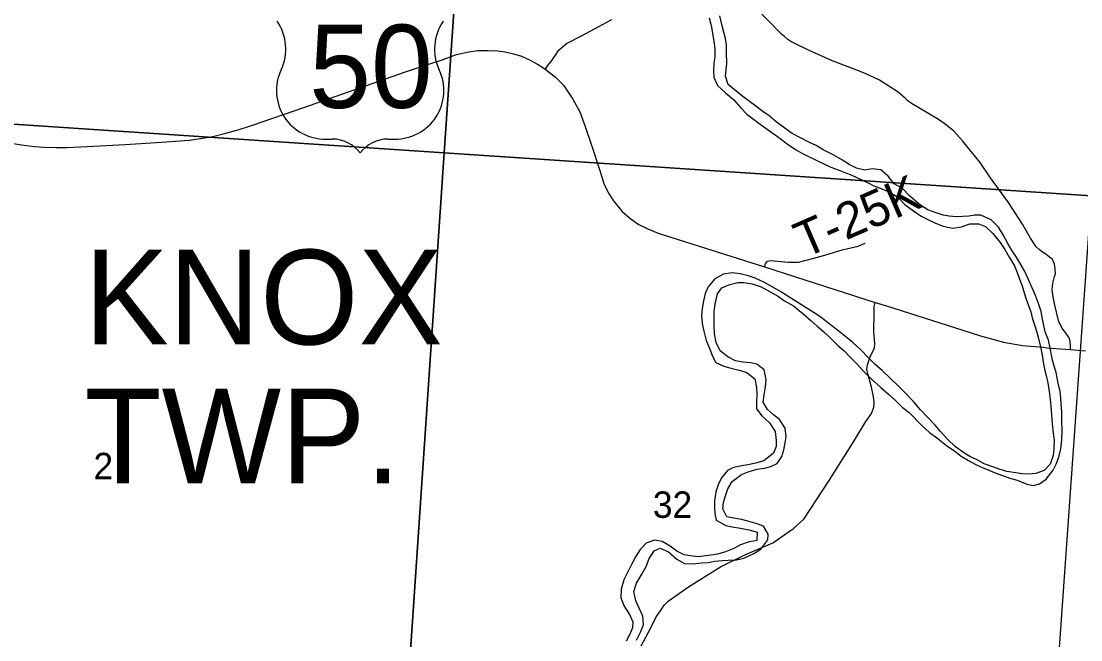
# Model space of a CAD drawing. Extents: x 0 to 34, y 0 to 22.
# Drawn here: x 3.724 to 5.404, y 16.952 to 17.932 of the extents above; entities that cross this region are included whole.
import ezdxf

# ---------------------------------------------------------------- set-up
doc = ezdxf.new("R2010")
doc.units = 0
for name, color, linetype in [('GM_X_Corporation', 7, 'Continuous'), ('GM_X_County_Road', 7, 'Continuous'), ('GM_X_Major_River', 7, 'Continuous'), ('GM_X_Section_Text', 7, 'Continuous'), ('GM_X_State_Route', 7, 'Continuous'), ('GM_X_Township_Road', 7, 'Continuous'), ('GM_X_Township_Road_Text', 7, 'Continuous'), ('GM_X_Township_Text', 7, 'Continuous'), ('GM_X_US_Location', 7, 'Continuous'), ('GM_X_US_Route', 7, 'Continuous'), ('GM_X_US_Shield', 7, 'Continuous')]:
    doc.layers.add(name, color=color, linetype=linetype)

msp = doc.modelspace()

# ---------------------------------------------------------------- linework, layer by layer
at = {"layer": 'GM_X_Corporation'}
for points in [[(4.465, 18.749), (4.3947, 17.724), (3.3856, 17.7912), (3.4438, 18.6342), (3.459, 18.812)], [(5.4857, 18.6848), (5.4744, 18.5035), (5.4208, 17.6557), (4.3947, 17.724), (4.465, 18.749)], [(3.3856, 17.7912), (4.3947, 17.724), (4.3249, 16.693), (3.312, 16.7534)], [(5.4208, 17.6557), (5.3461, 16.6042), (4.3249, 16.693), (4.3947, 17.724)]]:
    msp.add_lwpolyline(points, close=True, dxfattribs=at)
at = {"layer": 'GM_X_County_Road'}
msp.add_lwpolyline([(4.6598, 17.9349), (4.6119, 17.9087), (4.5894, 17.8969), (4.5814, 17.8905), (4.5749, 17.885), (4.5638, 17.8684), (4.5582, 17.8618), (4.5548, 17.8564)], dxfattribs=at)
at = {"layer": 'GM_X_Major_River'}
for points in [[(4.8149, 17.9379), (4.8179, 17.9258), (4.8209, 17.9102), (4.8224, 17.9004), (4.8239, 17.8886), (4.8239, 17.8753), (4.8224, 17.8658), (4.8216, 17.8533)], [(4.8418, 17.8548), (4.8429, 17.8662), (4.8425, 17.8825), (4.8422, 17.8947), (4.841, 17.9053), (4.8358, 17.925), (4.8316, 17.941)], [(4.8216, 17.8533), (4.8224, 17.8438), (4.8284, 17.8305), (4.8406, 17.8191), (4.8539, 17.8081), (4.8649, 17.7952), (4.8747, 17.7853), (4.885, 17.7774), (4.896, 17.7694), (4.9108, 17.7587), (4.9233, 17.7496), (4.9388, 17.7382), (4.9521, 17.7291), (4.9631, 17.723), (4.9867, 17.7112), (4.9977, 17.7059), (5.0079, 17.7014), (5.0197, 17.6968), (5.0299, 17.6926), (5.0413, 17.6884), (5.066, 17.677), (5.0762, 17.6717), (5.0888, 17.6668), (5.1028, 17.6603), (5.1142, 17.6535), (5.1252, 17.6421), (5.1389, 17.6322), (5.151, 17.6235), (5.1616, 17.6181), (5.1738, 17.6124), (5.1859, 17.6079), (5.2007, 17.6044), (5.2152, 17.6067), (5.2281, 17.6113), (5.2425, 17.6112), (5.2531, 17.6071), (5.2649, 17.5961), (5.2763, 17.5816), (5.2838, 17.5706), (5.2907, 17.5588), (5.299, 17.5448), (5.3036, 17.5345), (5.307, 17.5235), (5.3111, 17.5133), (5.3145, 17.5023), (5.3179, 17.492), (5.3213, 17.4822), (5.3248, 17.4719), (5.3274, 17.4624), (5.3308, 17.4514), (5.3346, 17.44), (5.3372, 17.4298), (5.3406, 17.4165), (5.3429, 17.4032), (5.3444, 17.3922), (5.3467, 17.3812), (5.3493, 17.3709), (5.352, 17.3595), (5.3542, 17.3459), (5.3558, 17.3334), (5.3565, 17.322), (5.358, 17.3087), (5.3587, 17.2943), (5.3606, 17.2798), (5.3618, 17.2688), (5.3617, 17.2548), (5.3606, 17.2442), (5.3556, 17.2305), (5.3461, 17.2206), (5.3332, 17.2157), (5.3215, 17.215), (5.3108, 17.2154), (5.3013, 17.2169), (5.2869, 17.2192), (5.2748, 17.2226), (5.2649, 17.2264), (5.2508, 17.2313), (5.2391, 17.2378), (5.2281, 17.2427), (5.2186, 17.2484), (5.2057, 17.2579), (5.1928, 17.2705), (5.1818, 17.2826), (5.1731, 17.2925), (5.1503, 17.3168), (5.1389, 17.3301), (5.1245, 17.3445), (5.115, 17.3544), (5.1025, 17.3662), (5.0896, 17.3783), (5.0775, 17.389), (5.0684, 17.3988), (5.0547, 17.4121), (5.0426, 17.4232), (5.0289, 17.4345), (5.0164, 17.4448), (5.0027, 17.4551), (4.9921, 17.4634), (4.9815, 17.4706), (4.969, 17.4782), (4.9553, 17.487)], [(4.986, 17.4494), (4.9966, 17.4403), (5.0065, 17.4315), (5.0186, 17.4194), (5.0289, 17.4103), (5.0384, 17.4004), (5.049, 17.3897), (5.0589, 17.3784), (5.0718, 17.3658), (5.0873, 17.3521), (5.0994, 17.3415), (5.1104, 17.3313), (5.1211, 17.321), (5.1321, 17.3123), (5.1522, 17.2921), (5.1643, 17.2807), (5.1776, 17.2712), (5.1916, 17.2599), (5.2038, 17.2519), (5.2144, 17.2435), (5.2262, 17.2363), (5.2368, 17.2306), (5.2467, 17.2257), (5.2584, 17.2211), (5.2713, 17.2158), (5.2816, 17.212), (5.2918, 17.2085), (5.3032, 17.2051), (5.3188, 17.1987), (5.3294, 17.1971), (5.3389, 17.1994), (5.3495, 17.207), (5.3602, 17.2214), (5.3651, 17.2309), (5.3693, 17.2415), (5.3728, 17.2552), (5.3743, 17.2692), (5.3747, 17.2844), (5.3743, 17.2988), (5.3743, 17.3136), (5.3732, 17.3258), (5.3725, 17.3356), (5.3713, 17.3459), (5.3683, 17.3592), (5.3653, 17.3759), (5.3623, 17.3857), (5.3596, 17.3956), (5.3555, 17.4146), (5.3528, 17.4271), (5.3479, 17.4404), (5.3456, 17.4506), (5.3437, 17.4605), (5.3415, 17.4723), (5.3373, 17.4852), (5.3324, 17.4977), (5.321, 17.5243), (5.3149, 17.5372), (5.3077, 17.5497), (5.3013, 17.56), (5.2945, 17.5702), (5.2888, 17.5801), (5.2812, 17.5941), (5.2736, 17.6063), (5.2619, 17.6177), (5.2455, 17.6253), (5.2361, 17.6249), (5.2266, 17.6238), (5.2171, 17.623), (5.2072, 17.6223), (5.1954, 17.6234), (5.1859, 17.625), (5.1734, 17.6295), (5.1616, 17.6337), (5.1499, 17.6409), (5.1339, 17.6546), (5.121, 17.6679), (5.1081, 17.6747), (5.099, 17.6869), (5.0873, 17.6971), (5.0736, 17.6987), (5.0618, 17.6964), (5.0485, 17.6994), (5.0368, 17.7055), (5.0262, 17.7124), (5.0129, 17.72), (4.9958, 17.7287), (4.9848, 17.7355), (4.9738, 17.7405), (4.9609, 17.7473), (4.9468, 17.7545), (4.9351, 17.7629), (4.9214, 17.7732), (4.91, 17.7823), (4.8998, 17.7895), (4.8892, 17.7978), (4.8766, 17.807), (4.866, 17.8149), (4.8546, 17.8241), (4.8452, 17.832), (4.841, 17.8453), (4.8418, 17.8548)], [(4.9553, 17.487), (4.9443, 17.4934), (4.9295, 17.5033), (4.9158, 17.5109), (4.9018, 17.5189), (4.8878, 17.5254), (4.8775, 17.5292), (4.8642, 17.5322), (4.8513, 17.5337), (4.8373, 17.5318), (4.8236, 17.5239), (4.8133, 17.5117), (4.8087, 17.5011), (4.8053, 17.4867), (4.8038, 17.4765), (4.803, 17.4666), (4.8041, 17.4537), (4.8064, 17.4412), (4.8102, 17.4264), (4.8159, 17.4127), (4.82, 17.4017), (4.8257, 17.3918), (4.8382, 17.3857), (4.8515, 17.3823), (4.8652, 17.3789), (4.8754, 17.3755), (4.8872, 17.3656), (4.8902, 17.3519), (4.8906, 17.3424), (4.8898, 17.3276), (4.8898, 17.3181), (4.8985, 17.3071), (4.9107, 17.2961), (4.9194, 17.2824), (4.9213, 17.268), (4.9213, 17.2585), (4.9171, 17.2479), (4.9015, 17.2361), (4.889, 17.2324), (4.8764, 17.2297), (4.8666, 17.2282), (4.8537, 17.2252), (4.8438, 17.2206), (4.8343, 17.2089), (4.8293, 17.1979), (4.8255, 17.1869), (4.8236, 17.1728), (4.8236, 17.1626), (4.824, 17.152), (4.8262, 17.1421), (4.8414, 17.1333), (4.8513, 17.1314), (4.8646, 17.1292), (4.8786, 17.1265), (4.8908, 17.1227), (4.8907, 17.1098), (4.8767, 17.1071), (4.8645, 17.103), (4.8539, 17.0969), (4.841, 17.0916), (4.8281, 17.0882), (4.8178, 17.0867), (4.7981, 17.0837), (4.7886, 17.0848), (4.7753, 17.0871), (4.7635, 17.0928), (4.7533, 17.1008), (4.7404, 17.108), (4.7282, 17.1103), (4.7149, 17.1053), (4.7054, 17.0955), (4.6982, 17.0837), (4.6917, 17.0716), (4.6796, 17.0473), (4.6754, 17.0325), (4.675, 17.0188), (4.6799, 17.0056), (4.6886, 16.9926), (4.6939, 16.9809), (4.6935, 16.9714), (4.6886, 16.96), (4.6833, 16.9501)], [(4.6996, 16.952), (4.7064, 16.9653), (4.711, 16.9763), (4.7099, 16.9896), (4.7038, 17.0025), (4.6989, 17.0143), (4.6955, 17.0287), (4.6997, 17.042), (4.708, 17.0564), (4.7153, 17.0697), (4.7195, 17.0803), (4.7275, 17.0932), (4.7373, 17.0977), (4.7502, 17.092), (4.7639, 17.0803), (4.776, 17.0734), (4.7893, 17.0727), (4.8034, 17.0742), (4.8136, 17.0749), (4.8239, 17.0772), (4.8357, 17.0779), (4.8451, 17.0783), (4.8584, 17.0791), (4.8698, 17.0817), (4.8858, 17.0889), (4.8968, 17.0961), (4.9082, 17.1105), (4.9086, 17.12), (4.901, 17.1325), (4.8912, 17.136), (4.876, 17.1405), (4.8661, 17.1428), (4.8566, 17.1443), (4.8429, 17.147), (4.8365, 17.1599), (4.8376, 17.1698), (4.8407, 17.1804), (4.8445, 17.1914), (4.8514, 17.2032), (4.8662, 17.2145), (4.8768, 17.2187), (4.8905, 17.2225), (4.9026, 17.2244), (4.9125, 17.2267), (4.9228, 17.2316), (4.9304, 17.243), (4.9334, 17.2536), (4.9353, 17.2646), (4.9372, 17.2741), (4.9357, 17.2877), (4.9266, 17.3014), (4.9168, 17.309), (4.9073, 17.317), (4.9005, 17.3291), (4.902, 17.3405), (4.9043, 17.353), (4.9051, 17.3648), (4.902, 17.38), (4.8906, 17.3891), (4.8812, 17.391), (4.8686, 17.3925), (4.8569, 17.3944), (4.8447, 17.4009), (4.8326, 17.4104), (4.8258, 17.4233), (4.8235, 17.4374), (4.8227, 17.451), (4.8228, 17.4628), (4.8231, 17.473), (4.8243, 17.4844), (4.8281, 17.5007), (4.835, 17.5102), (4.8475, 17.5155), (4.8604, 17.5185), (4.8699, 17.5185), (4.8832, 17.5166), (4.8976, 17.5117), (4.9116, 17.5037), (4.9234, 17.4972), (4.9344, 17.4896), (4.9485, 17.4813), (4.9633, 17.4691), (4.9765, 17.4577), (4.986, 17.4494)]]:
    msp.add_lwpolyline(points, dxfattribs=at)
at = {"layer": 'GM_X_State_Route'}
msp.add_lwpolyline([(5.3878, 17.4121), (5.3878, 17.4179), (5.3875, 17.4249), (5.386, 17.431), (5.3813, 17.4379), (5.3749, 17.4459), (5.3696, 17.4561), (5.3631, 17.4828), (5.3603, 17.4959), (5.3587, 17.5069), (5.3599, 17.5173), (5.3612, 17.5218), (5.3628, 17.5279), (5.3639, 17.5322), (5.3637, 17.5394), (5.3632, 17.5447), (5.3615, 17.5505), (5.3589, 17.5553), (5.3549, 17.5587), (5.3489, 17.5632), (5.3435, 17.5664), (5.3381, 17.5706), (5.3336, 17.575), (5.3247, 17.5887), (5.3118, 17.611), (5.2894, 17.6451), (5.2611, 17.6842), (5.2445, 17.7087), (5.2168, 17.7429), (5.2031, 17.7583), (5.1893, 17.7696), (5.1788, 17.777), (5.1642, 17.7852), (5.1472, 17.7952), (5.1359, 17.8023), (5.1302, 17.8064), (5.1265, 17.81), (5.1144, 17.8199), (5.1001, 17.8298), (5.0849, 17.8392), (5.0623, 17.8495), (5.0516, 17.8539), (5.0092, 17.87), (4.9733, 17.8859), (4.9507, 17.8971), (4.9444, 17.9004), (4.9398, 17.9037), (4.9343, 17.908), (4.9296, 17.912), (4.8885, 17.9544)], dxfattribs=at)
at = {"layer": 'GM_X_Township_Road'}
for points in [[(4.9029, 17.5433), (4.9041, 17.5484), (4.9074, 17.5521), (4.9127, 17.5535), (4.9231, 17.5525), (4.9405, 17.5506), (4.9567, 17.5505), (4.9811, 17.557), (4.9983, 17.5619), (5.0257, 17.5705), (5.0396, 17.5736), (5.0513, 17.576), (5.0622, 17.5807)], [(4.7072, 16.9428), (4.722, 16.9703), (4.731, 16.9888), (4.7376, 16.9981), (4.7437, 17.0071), (4.75, 17.0137), (4.7821, 17.0364), (4.8331, 17.0679), (4.8707, 17.0864), (4.9159, 17.106), (4.9488, 17.1288), (4.965, 17.1436), (5.0055, 17.205), (5.0448, 17.2677), (5.0636, 17.2985), (5.0722, 17.3108), (5.076, 17.3207), (5.0767, 17.3288), (5.0758, 17.338), (5.072, 17.3546), (5.0672, 17.372), (5.0652, 17.3805), (5.0662, 17.3882), (5.0707, 17.4025), (5.0769, 17.4146), (5.0777, 17.422), (5.0763, 17.4409), (5.0765, 17.4712), (5.0768, 17.4803), (5.0781, 17.4867)]]:
    msp.add_lwpolyline(points, dxfattribs=at)
at = {"layer": 'GM_X_US_Route'}
for points in [[(3.7049, 17.74), (3.7246, 17.7368), (3.7449, 17.7339), (3.7594, 17.7329), (3.7797, 17.7326), (3.7966, 17.7326), (3.8288, 17.7339), (3.8887, 17.7372), (3.9542, 17.7413), (3.9901, 17.7441), (4.0081, 17.7465), (4.0279, 17.7497), (4.0485, 17.7551), (4.0695, 17.7607), (4.0846, 17.7657), (4.0909, 17.7679), (4.1719, 17.796), (4.3317, 17.8518), (4.3767, 17.8667), (4.3914, 17.8712), (4.4143, 17.8795), (4.4336, 17.8838), (4.4483, 17.8859), (4.4643, 17.8862), (4.4796, 17.8855), (4.4915, 17.884), (4.5047, 17.881), (4.5172, 17.8769), (4.5302, 17.8715), (4.5428, 17.8645), (4.5495, 17.8602), (4.5548, 17.8564), (4.5706, 17.8444), (4.5837, 17.8309), (4.5988, 17.8092), (4.6101, 17.7888), (4.6181, 17.7658), (4.6281, 17.7363), (4.6414, 17.6958), (4.648, 17.6751), (4.6551, 17.6602), (4.6633, 17.6477), (4.6766, 17.6317), (4.6885, 17.6211), (4.7024, 17.6108), (4.7176, 17.6033), (4.7342, 17.5965), (4.7555, 17.5897), (4.9029, 17.5433), (5.0781, 17.4867), (5.0961, 17.4815), (5.2174, 17.4428), (5.2451, 17.4339), (5.2815, 17.424), (5.3119, 17.4187), (5.3444, 17.4158), (5.3503, 17.4151), (5.3721, 17.4135), (5.3878, 17.4121)], [(5.3878, 17.4121), (5.4117, 17.4102)]]:
    msp.add_lwpolyline(points, dxfattribs=at)
at = {"layer": 'GM_X_US_Shield'}
for p, q in [((4.2066, 17.7457), (4.2176, 17.7457)), ((4.3054, 17.7457), (4.3164, 17.7457))]:
    msp.add_line(p, q, dxfattribs=at)
for centre, radius, start, end in [((4.0667, 17.8884), 0.0769, 334.5471, 35.0009), ((4.4563, 17.8884), 0.0769, 144.9991, 205.4529), ((4.2057, 17.8226), 0.0769, 154.8319, 270.6383), ((4.3173, 17.8226), 0.0769, 269.3617, 25.1681), ((4.2176, 17.6908), 0.0549, 36.8699, 90), ((4.3054, 17.6908), 0.0549, 90, 143.1301)]:
    msp.add_arc(centre, radius, start, end, dxfattribs=at)

# ---------------------------------------------------------------- texts
at = {"layer": 'GM_X_Section_Text'}
for s, height, p in [('2', 0.0419, (3.8386, 17.2067)), ('32', 0.04186, (4.7257, 17.1456))]:
    msp.add_text(s, height=height, rotation=0, dxfattribs=at).set_placement(p)
at = {"layer": 'GM_X_Township_Road_Text'}
msp.add_text('T-25K', height=0.05682, rotation=23.4674, dxfattribs=at).set_placement((4.9659, 17.5564))
at = {"layer": 'GM_X_Township_Text'}
for s, p in [('KNOX', (3.8242, 17.4203)), ('TWP.', (3.8242, 17.2003))]:
    msp.add_text(s, height=0.15, rotation=0, dxfattribs=at).set_placement(p)
at = {"layer": 'GM_X_US_Location'}
for s in ['0', '/']:
    msp.add_text(s, height=0.000189, dxfattribs=at).set_placement((4.2614, 17.86))
msp.add_text('50', height=0.000189, rotation=0, dxfattribs=at).set_placement((4.2223, 17.8208))
at = {"layer": 'GM_X_US_Shield'}
msp.add_text('50', height=0.13184, dxfattribs=at).set_placement((4.1806, 17.7951))

doc.saveas('drawing.dxf')
